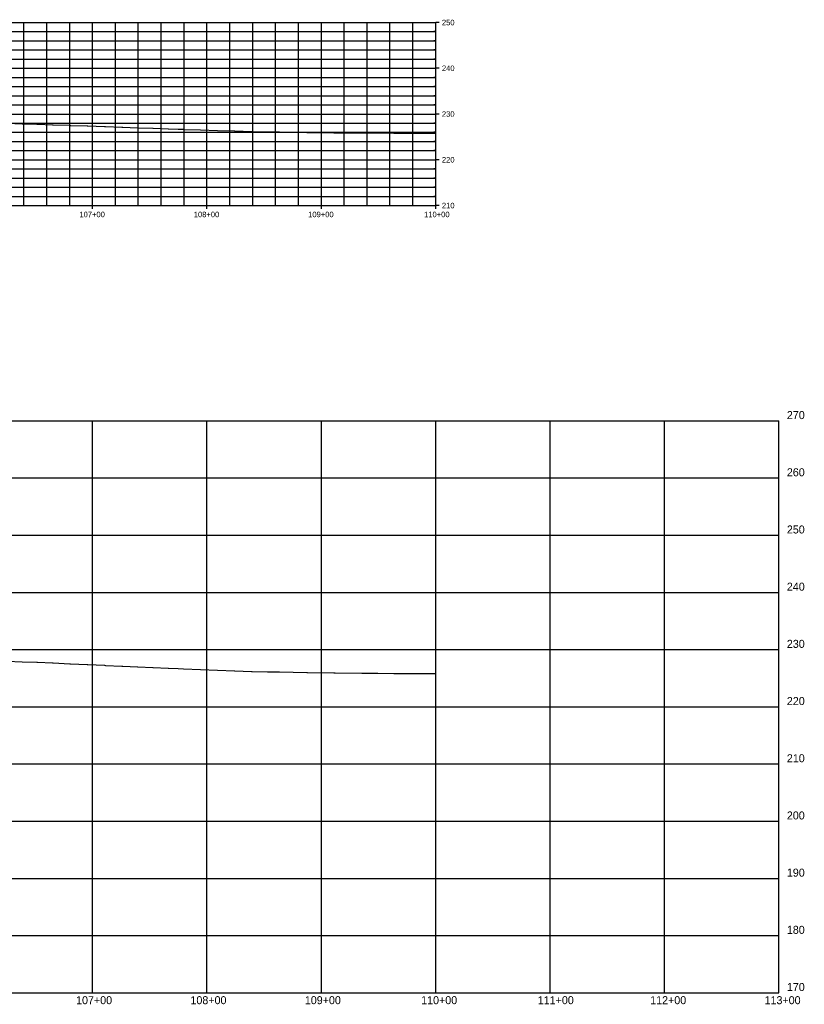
# Model space of a CAD drawing. Extents: x 1805251 to 1808760, y 516965 to 518393.
# Drawn here: x 1806108 to 1806794, y 517532 to 518393 of the extents above; entities that cross this region are included whole.
import ezdxf

# ---------------------------------------------------------------- set-up
doc = ezdxf.new("R2010")
doc.units = 0
for name, color, linetype in [('R_Axis', 7, 'Continuous'), ('R_Axis Annot', 7, 'Continuous'), ('R_Exist Surface', 7, 'Continuous'), ('R_Grid', 7, 'Continuous')]:
    doc.layers.add(name, color=color, linetype=linetype)

msp = doc.modelspace()

# ---------------------------------------------------------------- linework, layer by layer
at = {"layer": 'R_Axis'}
for p, q in [((1806472.2, 518230.42), (1806472.2, 518390.42)), ((1805472.2, 518230.42), (1806472.2, 518230.42)), ((1806772.2, 517542.24), (1806772.2, 518042.24)), ((1805272.2, 517542.24), (1806772.2, 517542.24))]:
    msp.add_line(p, q, dxfattribs=at)
at = {"layer": 'R_Exist Surface'}
for points in [[(1806097.39, 518302.36), (1806110.51, 518301.95), (1806123.49, 518301.54), (1806124.14, 518301.52), (1806137.06, 518301.11), (1806137.78, 518301.09), (1806152.21, 518300.55), (1806152.98, 518300.52), (1806167.43, 518299.99), (1806168.18, 518299.96), (1806182.64, 518299.42), (1806183.38, 518299.4), (1806197.86, 518298.86), (1806198.58, 518298.83), (1806211.41, 518298.4), (1806211.86, 518298.38), (1806224.86, 518297.95), (1806225.15, 518297.94), (1806238.32, 518297.49), (1806238.44, 518297.49), (1806247.02, 518297.2), (1806251.67, 518297.04), (1806251.74, 518297.03), (1806266.52, 518296.57), (1806266.62, 518296.57), (1806281.38, 518296.11), (1806281.51, 518296.1), (1806296.23, 518295.64), (1806296.4, 518295.64), (1806296.56, 518295.63), (1806311.28, 518295.17), (1806311.6, 518295.17), (1806325.22, 518294.94), (1806335.54, 518294.74), (1806335.71, 518294.74), (1806359.43, 518294.29), (1806359.99, 518294.29), (1806383.2, 518294.1), (1806383.76, 518294.09), (1806384.33, 518294.08), (1806407.53, 518293.89), (1806407.74, 518293.89), (1806421.57, 518293.84), (1806421.72, 518293.84), (1806435.62, 518293.78), (1806435.7, 518293.78), (1806449.66, 518293.73), (1806449.68, 518293.73), (1806453.85, 518293.71), (1806463.7, 518293.67), (1806463.78, 518293.67), (1806468.58, 518293.65), (1806472.2, 518293.63)], [(1806097.39, 517832.17), (1806110.51, 517831.65), (1806123.49, 517831.14), (1806124.14, 517831.11), (1806137.06, 517830.61), (1806137.78, 517830.58), (1806152.21, 517829.91), (1806152.98, 517829.87), (1806167.43, 517829.2), (1806168.18, 517829.17), (1806182.64, 517828.5), (1806183.38, 517828.46), (1806197.86, 517827.79), (1806198.58, 517827.76), (1806211.41, 517827.22), (1806211.86, 517827.2), (1806224.86, 517826.65), (1806225.15, 517826.64), (1806238.32, 517826.08), (1806238.44, 517826.08), (1806247.02, 517825.72), (1806251.67, 517825.51), (1806251.74, 517825.51), (1806266.52, 517824.93), (1806266.62, 517824.93), (1806281.38, 517824.35), (1806281.51, 517824.35), (1806296.23, 517823.77), (1806296.4, 517823.76), (1806296.56, 517823.76), (1806311.28, 517823.18), (1806311.6, 517823.18), (1806325.22, 517822.89), (1806335.54, 517822.64), (1806335.71, 517822.64), (1806359.43, 517822.08), (1806359.99, 517822.07), (1806383.2, 517821.84), (1806383.76, 517821.82), (1806384.33, 517821.81), (1806407.53, 517821.58), (1806407.74, 517821.58), (1806421.57, 517821.51), (1806421.72, 517821.51), (1806435.62, 517821.45), (1806435.7, 517821.45), (1806449.66, 517821.38), (1806449.68, 517821.38), (1806453.85, 517821.36), (1806463.7, 517821.3), (1806463.78, 517821.3), (1806468.58, 517821.28), (1806472.2, 517821.25)]]:
    msp.add_lwpolyline(points, dxfattribs=at)
at = {"layer": 'R_Grid'}
for p, q in [((1805472.2, 518390.42), (1806472.2, 518390.42)), ((1805472.2, 518390.42), (1806472.2, 518390.42)), ((1806112.2, 518230.42), (1806112.2, 518390.42)), ((1806132.2, 518230.42), (1806132.2, 518390.42)), ((1806152.2, 518230.42), (1806152.2, 518390.42)), ((1806172.2, 518230.42), (1806172.2, 518390.42)), ((1806192.2, 518230.42), (1806192.2, 518390.42)), ((1806212.2, 518230.42), (1806212.2, 518390.42)), ((1806232.2, 518230.42), (1806232.2, 518390.42)), ((1806252.2, 518230.42), (1806252.2, 518390.42)), ((1806272.2, 518230.42), (1806272.2, 518390.42)), ((1806292.2, 518230.42), (1806292.2, 518390.42)), ((1806312.2, 518230.42), (1806312.2, 518390.42)), ((1806332.2, 518230.42), (1806332.2, 518390.42)), ((1806352.2, 518230.42), (1806352.2, 518390.42)), ((1806372.2, 518230.42), (1806372.2, 518390.42)), ((1806392.2, 518230.42), (1806392.2, 518390.42)), ((1806412.2, 518230.42), (1806412.2, 518390.42)), ((1806432.2, 518230.42), (1806432.2, 518390.42)), ((1806452.2, 518230.42), (1806452.2, 518390.42)), ((1806475.2, 518390.42), (1806472.2, 518390.42)), ((1806475.2, 518390.42), (1806472.2, 518390.42)), ((1805472.2, 518382.42), (1806472.2, 518382.42)), ((1806472.2, 518382.42), (1806470.7, 518382.42)), ((1805472.2, 518374.42), (1806472.2, 518374.42)), ((1806472.2, 518374.42), (1806470.7, 518374.42)), ((1805472.2, 518366.42), (1806472.2, 518366.42)), ((1806472.2, 518366.42), (1806470.7, 518366.42)), ((1805472.2, 518358.42), (1806472.2, 518358.42)), ((1806472.2, 518358.42), (1806470.7, 518358.42)), ((1805472.2, 518350.42), (1806472.2, 518350.42)), ((1806475.2, 518350.42), (1806472.2, 518350.42)), ((1805472.2, 518342.42), (1806472.2, 518342.42)), ((1806472.2, 518342.42), (1806470.7, 518342.42)), ((1805472.2, 518334.42), (1806472.2, 518334.42)), ((1806472.2, 518334.42), (1806470.7, 518334.42)), ((1805472.2, 518326.42), (1806472.2, 518326.42)), ((1805472.2, 518318.42), (1806472.2, 518318.42)), ((1806472.2, 518326.42), (1806470.7, 518326.42)), ((1806472.2, 518318.42), (1806470.7, 518318.42)), ((1805472.2, 518310.42), (1806472.2, 518310.42)), ((1806475.2, 518310.42), (1806472.2, 518310.42)), ((1805472.2, 518302.42), (1806472.2, 518302.42)), ((1806472.2, 518302.42), (1806470.7, 518302.42)), ((1805472.2, 518294.42), (1806472.2, 518294.42)), ((1806472.2, 518294.42), (1806470.7, 518294.42)), ((1805472.2, 518286.42), (1806472.2, 518286.42)), ((1806472.2, 518286.42), (1806470.7, 518286.42)), ((1805472.2, 518278.42), (1806472.2, 518278.42)), ((1806472.2, 518278.42), (1806470.7, 518278.42)), ((1805472.2, 518270.42), (1806472.2, 518270.42)), ((1806475.2, 518270.42), (1806472.2, 518270.42)), ((1805472.2, 518262.42), (1806472.2, 518262.42)), ((1806472.2, 518262.42), (1806470.7, 518262.42)), ((1805472.2, 518254.42), (1806472.2, 518254.42)), ((1806472.2, 518254.42), (1806470.7, 518254.42)), ((1805472.2, 518246.42), (1806472.2, 518246.42)), ((1806472.2, 518246.42), (1806470.7, 518246.42)), ((1805472.2, 518238.42), (1806472.2, 518238.42)), ((1806472.2, 518238.42), (1806470.7, 518238.42)), ((1806172.2, 518227.42), (1806172.2, 518230.42)), ((1806272.2, 518227.42), (1806272.2, 518230.42)), ((1806372.2, 518227.42), (1806372.2, 518230.42)), ((1806475.2, 518230.42), (1806472.2, 518230.42)), ((1806472.2, 518227.42), (1806472.2, 518230.42)), ((1805272.2, 518042.24), (1806772.2, 518042.24)), ((1805272.2, 518042.24), (1806772.2, 518042.24)), ((1806172.2, 517542.24), (1806172.2, 518042.24)), ((1806272.2, 517542.24), (1806272.2, 518042.24)), ((1806372.2, 517542.24), (1806372.2, 518042.24)), ((1806472.2, 517542.24), (1806472.2, 518042.24)), ((1806572.2, 517542.24), (1806572.2, 518042.24)), ((1806672.2, 517542.24), (1806672.2, 518042.24)), ((1805272.2, 517992.24), (1806772.2, 517992.24)), ((1805272.2, 517942.24), (1806772.2, 517942.24)), ((1805272.2, 517892.24), (1806772.2, 517892.24)), ((1805272.2, 517842.24), (1806772.2, 517842.24)), ((1805272.2, 517792.24), (1806772.2, 517792.24)), ((1805272.2, 517742.24), (1806772.2, 517742.24)), ((1805272.2, 517692.24), (1806772.2, 517692.24)), ((1805272.2, 517642.24), (1806772.2, 517642.24)), ((1805272.2, 517592.24), (1806772.2, 517592.24))]:
    msp.add_line(p, q, dxfattribs=at)

# ---------------------------------------------------------------- texts
at = {"layer": 'R_Axis Annot'}
for s, height, p in [('250', 4.8, (1806477.6, 518388.02)), ('240', 4.8, (1806477.6, 518348.02)), ('230', 4.8, (1806477.6, 518308.02)), ('220', 4.8, (1806477.6, 518268.02)), ('210', 4.8, (1806477.6, 518228.02)), ('107+00', 4.8, (1806160.66, 518220.22)), ('108+00', 4.8, (1806260.66, 518220.22)), ('109+00', 4.8, (1806360.66, 518220.22)), ('110+00', 4.8, (1806462.02, 518220.22)), ('270', 7, (1806779.2, 518043.74)), ('270', 7, (1806779.2, 518043.74)), ('260', 7, (1806779.2, 517993.74)), ('250', 7, (1806779.2, 517943.74)), ('240', 7, (1806779.2, 517893.74)), ('230', 7, (1806779.2, 517843.74)), ('220', 7, (1806779.2, 517793.74)), ('210', 7, (1806779.2, 517743.74)), ('200', 7, (1806779.2, 517693.74)), ('190', 7, (1806779.2, 517643.74)), ('180', 7, (1806779.2, 517593.74)), ('170', 7, (1806779.2, 517543.74)), ('107+00', 7, (1806157.77, 517532.24)), ('108+00', 7, (1806257.77, 517532.24)), ('109+00', 7, (1806357.77, 517532.24)), ('110+00', 7, (1806459.47, 517532.24)), ('111+00', 7, (1806561.41, 517532.24)), ('112+00', 7, (1806659.71, 517532.24)), ('113+00', 7, (1806759.71, 517532.24))]:
    msp.add_text(s, height=height, dxfattribs=at).set_placement(p)

doc.saveas('drawing.dxf')
